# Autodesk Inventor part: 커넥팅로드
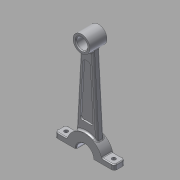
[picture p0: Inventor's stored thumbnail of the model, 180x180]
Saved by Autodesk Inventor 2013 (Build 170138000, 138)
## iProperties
Created: 2016-11
Part Number: 커넥팅로드
Material: 알루미늄 6061
Document SubType Name: Modeling
Designer: mduedu
Density: 2.71 g/cm^3
Mass: 62.0571 g
Surface Area: 108.143 cm^2
Volume: 22.8993 cm^3
Author: mduedu
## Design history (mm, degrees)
sketch "스케치1" dims "d0" = 42, "d3" = 20
  geometry: L1 (0, 0)-(0, 114); L2 (-7.5, 107.386)-(-12.5, 16.875); L3 (7.5, 107.386)-(12.5, 16.875); C1 r 10 at (0, 0); C2 r 6.5 at (0, 114); 3 further points
  constraints: 6 end point, 4 coincident, 2 centre point, 2 symmetric about line, 1 vertical, 6 other
  dimensions: "d1" = 20 diameter of C1; "d2" = 13 diameter of C2; "d4" = 114 distance of L1.start L1.end; "d6" = 12.5 distance from line of L1 L2.end; "d7" = 7.5 distance from line of L1 L2.start
extrude "돌출1" new body sketch "스케치1" stored distance "d8" = 13; taper "d9" = 0 deg
extrude "돌출2" join sketch "스케치1" stored distance "d10" = 20; taper "d11" = 0 deg
sketch "스케치2"
  geometry: L1 (-7.5, 107.386)-(-12.5, 16.875) reference; L2 (7.5, 107.386)-(12.5, 16.875) reference; A1 r 10 centre (0, 114) between (-7.5, 107.386) and (7.5, 107.386) reference; A2 r 21 centre (0, 0) between (-12.5, 16.875) and (12.5, 16.875) reference; 1 further point
extrude "돌출3" join sketch "스케치2" stored distance "d12" = 8; taper "d13" = 0 deg
sketch "스케치3"
  geometry: L1 (-7.5, 107.386)-(-12.5, 16.875) reference; L2 (7.5, 107.386)-(12.5, 16.875) reference; L3 (-4.209, 94.448)-(-7.768, 30.011); L4 (4.209, 94.448)-(7.768, 30.011); L5 (0, 94)-(0, 31); A1 r 10 centre (0, 114) between (-7.5, 107.386) and (7.5, 107.386) reference; A2 r 21 centre (0, 0) between (-12.5, 16.875) and (12.5, 16.875) reference; A3 r 20 centre (0, 114) between (-4.209, 94.448) and (4.209, 94.448); A4 r 31 centre (0, 0) between (7.768, 30.011) and (-7.768, 30.011); 1 further point
  constraints: 6 end point, 6 point on circle, 2 centre point, 2 parallel, 1 symmetric about line, 1 vertical alignment
  dimensions: "d18" = 10 radial gap between concentric circles of A3 A1; "d19" = 10 radial gap between concentric circles of A2 A4; "d20" = 4 distance between parallel lines of L3 L1
extrude "돌출4" cut sketch "스케치3" distance "d21" = 2; taper "d22" = 0 deg
fillet "모깎기1" dims "d23" = 3
fillet "모깎기2" dims "d24" = 2
fillet "모깎기3" dims "d25" = 2
chamfer "모따기1" distance "d26" = 1; stored, may be unused: second distance "d27" = 2, angle "d28" = 45 deg
sketch "스케치4"
  geometry: L1 (-35, -6)-(-20.125, -6); L2 (35, -6)-(35, 6); L3 (35, 6)-(20.125, 6); L4 (-35, 6)-(-35, -6); L5 (-35, -6)-(35, 6); L6 (35, -6)-(-35, 6); L7 (-20.125, 6)-(-35, 6); L8 (20.125, 6)-(-20.125, 6); L9 (20.125, -6)-(35, -6); L10 (-20.125, -6)-(20.125, -6); A1 r 21 centre (0, 0) between (-20.125, 6) and (20.125, 6) reference; 1 further point
  constraints: 20 end point, 10 parallel, 4 point on circle, 3 horizontal, 3 perpendicular, 2 midpoint
  dimensions: "d29" = 70 distance of L1.start L2.start; "d31" = 12 distance of L2.start L2.end
extrude "돌출5" join sketch "스케치4" stored distance "d32" = 0; taper "d33" = 0 deg
fillet "모깎기4" dims "d34" = 3
fillet "모깎기5" dims "d35" = 1
fillet "모깎기6" dims "d36" = 1
sketch "스케치5"
  geometry: L1 (1, 0)-(1, 7) reference; L2 (-24, 13.5)-(-44, 13.5) reference; L3 (-44, -6.5)-(-24, -6.5) reference; L4 (-34, 13.5)-(-34, -6.5); 3 further points
  constraints: 2 end point, 2 midpoint, 1 horizontal alignment, 1 symmetric about line
  dimensions: "d37" = 7 distance from line of point (-6, 3.5) L1
feature "분할1"
sketch "스케치6"
  geometry: 2 further points
  constraints: 2 other
hole "구멍1" sketch "스케치6" at (-62, 3.5), (-6, 3.5) diameter "d38" = 4.5; stored, may be unused: countersink angle "d42" = 90 deg, drill point angle "d44" = 0 deg; dims "d39" = 6, "d40" = 4, "d41" = 2, "d43" = 8
node "솔리드1"
mirror "대칭1"
other parameters: "d16" = 4, "d17" = 4
